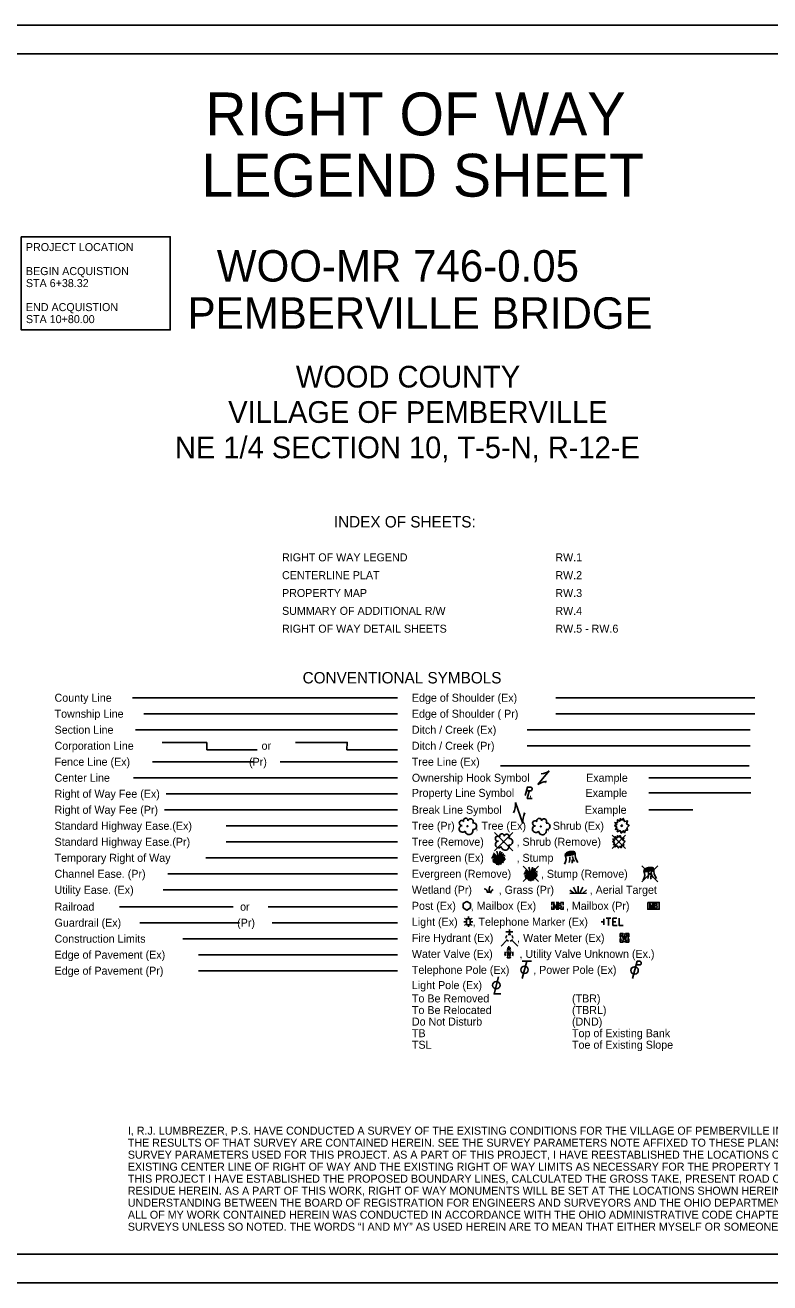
# Model space of a CAD drawing. Extents: x 0 to 34, y 0 to 22.
# Drawn here: x 9.38 to 22.4, y 0 to 22 of the extents above; entities that cross this region are included whole.
import ezdxf

# ---------------------------------------------------------------- set-up
doc = ezdxf.new("R2010")
doc.units = 0
for name, color, linetype in [('SH_Border', 7, 'Continuous'), ('SH_Cut_Line', 7, 'Continuous'), ('SH_Data', 7, 'Continuous'), ('SH_Text', 7, 'Continuous')]:
    doc.layers.add(name, color=color, linetype=linetype)

msp = doc.modelspace()

# ---------------------------------------------------------------- linework, layer by layer
at = {"layer": 'SH_Border'}
msp.add_lwpolyline([(1.5, 21.5), (33.5, 21.5), (33.5, 0.5), (1.5, 0.5)], close=True, dxfattribs=at)
at = {"layer": 'SH_Cut_Line'}
msp.add_lwpolyline([(0, 0), (34, 0), (34, 22), (0, 22)], close=True, dxfattribs=at)
at = {"layer": 'SH_Text'}
for p, q in [((11.254, 10.235), (15.893, 10.235)), ((18.66, 10.235), (22.143, 10.235)), ((11.452, 9.955), (15.893, 9.955)), ((18.66, 9.955), (22.143, 9.955)), ((11.31, 9.675), (15.893, 9.675)), ((18.159, 9.675), (22.059, 9.675)), ((11.774, 9.452), (12.556, 9.452)), ((12.556, 9.452), (12.556, 9.325)), ((12.556, 9.325), (13.437, 9.325)), ((18.159, 9.395), (22.059, 9.395)), ((11.607, 9.115), (13.38, 9.115)), ((13.837, 9.115), (15.893, 9.115)), ((17.692, 9.045), (22.042, 9.045)), ((11.275, 8.835), (15.893, 8.835)), ((18.347, 8.715), (18.547, 8.955)), ((18.447, 8.835), (18.447, 8.835)), ((20.29, 8.835), (22.072, 8.835)), ((18.147, 8.604), (18.212, 8.604)), ((11.843, 8.555), (15.893, 8.555)), ((17.954, 8.404), (18.084, 8.036)), ((18.187, 8.573), (18.187, 8.573)), ((20.29, 8.571), (22.072, 8.571)), ((11.815, 8.275), (15.893, 8.275)), ((18.019, 8.22), (18.019, 8.22)), ((20.29, 8.275), (21.055, 8.275)), ((12.893, 7.995), (15.893, 7.995)), ((12.893, 7.715), (15.893, 7.715)), ((17.587, 7.876), (17.908, 7.555)), ((17.908, 7.876), (17.587, 7.555)), ((17.748, 7.715), (17.748, 7.715)), ((19.646, 7.831), (19.878, 7.599)), ((19.878, 7.831), (19.646, 7.599)), ((19.762, 7.715), (19.762, 7.715)), ((17.658, 7.435), (17.56, 7.492)), ((17.658, 7.435), (17.571, 7.522)), ((17.658, 7.435), (17.627, 7.55)), ((17.658, 7.435), (17.69, 7.553)), ((17.658, 7.435), (17.724, 7.532)), ((17.658, 7.435), (17.75, 7.505)), ((12.539, 7.435), (15.893, 7.435)), ((17.535, 7.435), (17.658, 7.435)), ((17.658, 7.435), (17.548, 7.465)), ((17.658, 7.435), (17.551, 7.396)), ((17.658, 7.435), (17.559, 7.378)), ((17.658, 7.435), (17.56, 7.36)), ((17.658, 7.435), (17.584, 7.348)), ((17.658, 7.435), (17.6, 7.335)), ((17.658, 7.435), (17.616, 7.327)), ((17.658, 7.435), (17.627, 7.314)), ((17.658, 7.435), (17.645, 7.32)), ((17.658, 7.435), (17.777, 7.475)), ((17.658, 7.435), (17.771, 7.437)), ((17.658, 7.304), (17.658, 7.435)), ((17.658, 7.435), (17.681, 7.319)), ((17.658, 7.435), (17.706, 7.318)), ((17.658, 7.435), (17.722, 7.34)), ((17.658, 7.435), (17.748, 7.347)), ((17.658, 7.435), (17.754, 7.371)), ((17.658, 7.435), (17.77, 7.387)), ((17.658, 7.435), (17.779, 7.411)), ((18.088, 7.289), (18.356, 7.022)), ((18.356, 7.289), (18.088, 7.022)), ((18.222, 7.155), (18.191, 7.271)), ((18.222, 7.155), (18.254, 7.273)), ((18.932, 7.435), (18.932, 7.435)), ((20.168, 7.294), (20.446, 7.016)), ((20.446, 7.294), (20.168, 7.016)), ((11.876, 7.155), (15.893, 7.155)), ((18.099, 7.155), (18.222, 7.155)), ((18.222, 7.155), (18.112, 7.185)), ((18.222, 7.155), (18.115, 7.116)), ((18.222, 7.155), (18.123, 7.098)), ((18.222, 7.155), (18.124, 7.213)), ((18.222, 7.155), (18.124, 7.08)), ((18.222, 7.155), (18.135, 7.242)), ((18.222, 7.155), (18.148, 7.069)), ((18.222, 7.155), (18.164, 7.055)), ((18.222, 7.155), (18.18, 7.047)), ((18.222, 7.155), (18.191, 7.034)), ((18.222, 7.155), (18.209, 7.04)), ((18.222, 7.155), (18.288, 7.252)), ((18.222, 7.155), (18.314, 7.225)), ((18.222, 7.155), (18.341, 7.195)), ((18.222, 7.155), (18.335, 7.158)), ((18.222, 7.024), (18.222, 7.155)), ((18.222, 7.155), (18.245, 7.039)), ((18.222, 7.155), (18.27, 7.039)), ((18.222, 7.155), (18.286, 7.06)), ((18.222, 7.155), (18.312, 7.067)), ((18.222, 7.155), (18.318, 7.091)), ((18.222, 7.155), (18.334, 7.107)), ((18.222, 7.155), (18.343, 7.131)), ((18.222, 7.155), (18.222, 7.155)), ((20.307, 7.155), (20.307, 7.155)), ((20.307, 7.155), (20.307, 7.155)), ((11.793, 6.875), (15.893, 6.875)), ((18.975, 6.814), (18.907, 6.871)), ((19.024, 6.815), (18.972, 6.921)), ((19.054, 6.815), (19.052, 6.941)), ((19.084, 6.816), (19.133, 6.923)), ((19.132, 6.816), (19.199, 6.876)), ((18.665, 6.656), (18.715, 6.656)), ((18.908, 6.813), (19.2, 6.817)), ((11.031, 6.58), (13.018, 6.58)), ((13.627, 6.58), (15.893, 6.58)), ((17.083, 6.364), (17.064, 6.382)), ((17.131, 6.379), (17.131, 6.406)), ((17.197, 6.382), (17.179, 6.364)), ((18.665, 6.534), (18.715, 6.534)), ((18.69, 6.595), (18.69, 6.595)), ((20.369, 6.595), (20.369, 6.595)), ((11.386, 6.3), (13.128, 6.3)), ((13.698, 6.3), (15.893, 6.3)), ((17.079, 6.316), (17.052, 6.316)), ((17.083, 6.267), (17.064, 6.248)), ((17.131, 6.315), (17.131, 6.315)), ((17.131, 6.251), (17.131, 6.225)), ((17.197, 6.248), (17.179, 6.267)), ((17.21, 6.316), (17.183, 6.316)), ((17.849, 6.095), (17.849, 6.181)), ((19.503, 6.315), (19.454, 6.315)), ((19.503, 6.265), (19.503, 6.365)), ((12.137, 6.02), (15.893, 6.02)), ((17.807, 5.993), (17.703, 5.889)), ((17.909, 6.138), (17.789, 6.138)), ((17.849, 6.035), (17.849, 6.035)), ((17.849, 6.035), (17.849, 6.035)), ((17.891, 5.993), (17.995, 5.889)), ((19.862, 6.035), (19.862, 6.035)), ((12.41, 5.74), (15.893, 5.74)), ((17.872, 5.857), (17.808, 5.857)), ((17.84, 5.825), (17.84, 5.889)), ((17.84, 5.755), (17.84, 5.755)), ((18.153, 5.625), (18.072, 5.325)), ((18.233, 5.625), (18.073, 5.625)), ((20.082, 5.625), (20.001, 5.325)), ((20.065, 5.562), (20.124, 5.562)), ((20.082, 5.625), (20.124, 5.625)), ((12.41, 5.46), (15.893, 5.46))]:
    msp.add_line(p, q, dxfattribs=at)
for points in [[(9.311, 18.299), (11.916, 18.299), (11.916, 16.668), (9.311, 16.668)], [(20.269, 6.656), (20.469, 6.656), (20.469, 6.534), (20.269, 6.534)], [(17.097, 6.265), (17.164, 6.265), (17.164, 6.365), (17.097, 6.365)]]:
    msp.add_lwpolyline(points, close=True, dxfattribs=at)
for points in [[(14.11, 9.452), (15.014, 9.452), (15.008, 9.325), (15.893, 9.325)], [(18.126, 8.525), (18.165, 8.673), (18.217, 8.673)], [(18.201, 8.621), (18.161, 8.473), (18.248, 8.473)], [(19.811, 8.086), (19.841, 8.123), (19.862, 8.07), (19.917, 8.079), (19.9, 8.028), (19.947, 7.999), (19.904, 7.962), (19.917, 7.916), (19.879, 7.92), (19.863, 7.874), (19.841, 7.908), (19.807, 7.868), (19.786, 7.912), (19.735, 7.89), (19.744, 7.938), (19.704, 7.933), (19.728, 7.973), (19.689, 8.001), (19.726, 8.014), (19.696, 8.055), (19.742, 8.049), (19.741, 8.101), (19.778, 8.073), (19.789, 8.122), (19.811, 8.086)], [(19.759, 7.792), (19.784, 7.823), (19.802, 7.779), (19.848, 7.786), (19.834, 7.743), (19.874, 7.718), (19.838, 7.687), (19.848, 7.648), (19.816, 7.651), (19.803, 7.612), (19.784, 7.641), (19.755, 7.607), (19.737, 7.644), (19.694, 7.626), (19.702, 7.666), (19.668, 7.663), (19.688, 7.696), (19.655, 7.72), (19.686, 7.732), (19.661, 7.766), (19.7, 7.761), (19.699, 7.805), (19.731, 7.781), (19.74, 7.823), (19.759, 7.792)], [(17.038, 6.558), (17.103, 6.52), (17.167, 6.558), (17.167, 6.633), (17.103, 6.67), (17.038, 6.633), (17.038, 6.558)], [(18.59, 6.608), (18.59, 6.656), (18.639, 6.656)], [(18.626, 6.555), (18.626, 6.635), (18.655, 6.555), (18.682, 6.635), (18.682, 6.555)], [(18.742, 6.599), (18.745, 6.602), (18.747, 6.604), (18.748, 6.606), (18.748, 6.607), (18.75, 6.609), (18.75, 6.611), (18.752, 6.616), (18.752, 6.618), (18.752, 6.62), (18.751, 6.624), (18.75, 6.627), (18.748, 6.63), (18.745, 6.632), (18.742, 6.633), (18.741, 6.634), (18.738, 6.635), (18.707, 6.635), (18.707, 6.555), (18.742, 6.555), (18.746, 6.558), (18.75, 6.561), (18.753, 6.566), (18.755, 6.572), (18.755, 6.577), (18.755, 6.581), (18.754, 6.585), (18.752, 6.591), (18.748, 6.594), (18.742, 6.599), (18.707, 6.599)], [(18.741, 6.656), (18.79, 6.656), (18.79, 6.608)], [(20.304, 6.555), (20.304, 6.635), (20.333, 6.555), (20.36, 6.635), (20.36, 6.555)], [(20.42, 6.599), (20.423, 6.602), (20.425, 6.604), (20.426, 6.606), (20.427, 6.607), (20.428, 6.609), (20.428, 6.611), (20.43, 6.616), (20.43, 6.618), (20.43, 6.62), (20.429, 6.624), (20.428, 6.627), (20.426, 6.63), (20.423, 6.632), (20.42, 6.633), (20.419, 6.634), (20.416, 6.635), (20.385, 6.635), (20.385, 6.555), (20.42, 6.555), (20.424, 6.558), (20.428, 6.561), (20.431, 6.566), (20.433, 6.572), (20.434, 6.577), (20.434, 6.581), (20.432, 6.585), (20.43, 6.591), (20.427, 6.594), (20.42, 6.599), (20.385, 6.599)], [(18.639, 6.534), (18.59, 6.534), (18.59, 6.583)], [(18.79, 6.583), (18.79, 6.534), (18.741, 6.534)], [(19.544, 6.377), (19.622, 6.377)], [(19.584, 6.377), (19.584, 6.252)], [(19.729, 6.377), (19.661, 6.377), (19.661, 6.252), (19.734, 6.252)], [(19.661, 6.315), (19.71, 6.315)], [(19.769, 6.377), (19.769, 6.252), (19.837, 6.252)], [(19.842, 6.11), (19.787, 6.11), (19.787, 6.055)], [(19.787, 6.015), (19.787, 5.96), (19.842, 5.96)], [(19.829, 6.08), (19.846, 5.99), (19.862, 6.08), (19.879, 5.99), (19.896, 6.08)], [(19.937, 6.055), (19.937, 6.11), (19.882, 6.11)], [(19.882, 5.96), (19.937, 5.96), (19.937, 6.015)], [(17.808, 5.796), (17.824, 5.71), (17.84, 5.796), (17.856, 5.71), (17.872, 5.796)], [(17.66, 5.354), (17.581, 5.055), (17.699, 5.055)]]:
    msp.add_lwpolyline(points, dxfattribs=at)
for centre, radius in [((17.115, 7.987), 0.0084), ((18.399, 7.984), 0.0072), ((19.815, 7.995), 0.0115), ((17.748, 7.715), 0.0072), ((19.762, 7.715), 0.00979), ((19.862, 6.035), 0.0675), ((18.113, 5.475), 0.065), ((20.039, 5.465), 0.065), ((17.621, 5.206), 0.065)]:
    msp.add_circle(centre, radius, dxfattribs=at)
for centre, radius, start, end in [((18.389, 9.17), 0.267, 273.6945, 306.337), ((18.212, 8.639), 0.0345, 270.471, 81.3281), ((18.505, 8.5), 0.267, 93.6945, 126.337), ((17.622, 8.371), 0.334, 332.9422, 5.5848), ((18.416, 8.068), 0.334, 152.9422, 185.5848), ((17.029, 7.941), 0.0592, 96.1722, 320.5737), ((17.015, 8.043), 0.0441, 39.0625, 279.5412), ((17.085, 8.088), 0.0395, 354.0047, 205.9741), ((17.143, 7.909), 0.0685, 184.9476, 19.4572), ((17.169, 8.072), 0.0466, 323.83, 165.0376), ((17.218, 7.988), 0.0574, 259.1453, 101.4596), ((18.314, 7.937), 0.0592, 96.1722, 320.5737), ((18.3, 8.04), 0.0441, 39.0625, 279.5412), ((18.37, 8.085), 0.0395, 354.0047, 205.9741), ((18.428, 7.906), 0.0685, 184.9476, 19.4572), ((18.454, 8.069), 0.0466, 323.83, 165.0376), ((18.503, 7.985), 0.0574, 259.1453, 101.4596), ((17.662, 7.669), 0.0592, 96.1722, 320.5737), ((17.648, 7.771), 0.0441, 39.0625, 279.5412), ((17.718, 7.816), 0.0395, 354.0047, 205.9741), ((17.802, 7.8), 0.0466, 323.83, 165.0376), ((17.851, 7.716), 0.0574, 259.1453, 101.4596), ((17.776, 7.637), 0.0685, 184.9476, 19.4572), ((18.64, 7.418), 0.2, 331.5338, 20.9269), ((19.212, 7.492), 0.215, 171.4106, 219.9194), ((18.656, 7.437), 0.253, 340.7938, 3.5481), ((19.127, 7.395), 0.182, 178.7926, 197.1224), ((19.257, 7.538), 0.316, 194.9653, 212.1216), ((20.016, 7.138), 0.2, 331.5338, 20.9269), ((20.031, 7.157), 0.253, 340.7938, 3.5481), ((20.503, 7.115), 0.182, 178.7926, 197.1224), ((20.633, 7.258), 0.316, 194.9653, 212.1216), ((20.588, 7.212), 0.215, 171.4106, 219.9194), ((17.849, 6.035), 0.06, 140.021, 184.0629), ((17.849, 6.035), 0.06, 211.8788, 255.8479), ((17.849, 6.035), 0.06, 68.1395, 112.038), ((17.849, 6.035), 0.06, 283.8239, 329.9097), ((17.849, 6.035), 0.06, 356.0165, 39.9889), ((17.84, 5.755), 0.07, 150.0184, 209.9816), ((17.84, 5.755), 0.07, 60.0184, 120.0157), ((17.84, 5.755), 0.07, 330.0184, 29.9816), ((17.84, 5.755), 0.07, 239.9843, 299.9816), ((20.125, 5.593), 0.0319, 268.8767, 91.1233)]:
    msp.add_arc(centre, radius, start, end, dxfattribs=at)
for centre, major_axis in [((18.913, 7.511), (0.0868, 0.0187)), ((18.913, 7.511), (0.0651, 0.0141)), ((18.913, 7.511), (0.0488, 0.0105)), ((18.913, 7.511), (0.0275, 0.0059)), ((18.913, 7.511), (0.0154, 0.0033)), ((20.289, 7.231), (0.0868, 0.0187)), ((20.289, 7.231), (0.0651, 0.0141)), ((20.289, 7.231), (0.0488, 0.0105)), ((20.289, 7.231), (0.0275, 0.0059)), ((20.289, 7.231), (0.0154, 0.0033))]:
    msp.add_ellipse(centre, major_axis=major_axis, ratio=0.36865, dxfattribs=at)
for points in [[(17.407, 6.891), (17.448, 6.873), (17.466, 6.82)], [(17.494, 6.824), (17.494, 6.871), (17.5, 6.916), (17.509, 6.936)], [(17.522, 6.817), (17.534, 6.855), (17.563, 6.879)]]:
    msp.add_spline(points, degree=3, dxfattribs=at)

# ---------------------------------------------------------------- texts
at = {"layer": 'SH_Data'}
for s, height, p in [('RIGHT OF WAY', 0.75, (12.527, 20.072)), ('LEGEND SHEET', 0.75, (12.458, 19)), ('WOO-MR 746-0.05', 0.55, (12.732, 17.514)), ('PEMBERVILLE BRIDGE', 0.55, (12.221, 16.689)), ('WOOD COUNTY', 0.38, (14.114, 15.661)), ('VILLAGE OF PEMBERVILLE', 0.38, (12.931, 15.043)), ('NE 1/4 SECTION 10, T-5-N, R-12-E', 0.38, (11.998, 14.424)), ('INDEX OF SHEETS:', 0.2, (14.778, 13.213)), ('RIGHT OF WAY LEGEND', 0.14, (13.872, 12.621)), ('RW.1', 0.14, (18.653, 12.621)), ('CENTERLINE PLAT', 0.14, (13.872, 12.309)), ('RW.2', 0.14, (18.653, 12.309)), ('PROPERTY MAP', 0.14, (13.872, 11.997)), ('RW.3', 0.14, (18.653, 11.997)), ('SUMMARY OF ADDITIONAL R/W', 0.14, (13.872, 11.685)), ('RW.4', 0.14, (18.653, 11.685)), ('RIGHT OF WAY DETAIL SHEETS', 0.14, (13.872, 11.373)), ('RW.5 - RW.6', 0.14, (18.653, 11.373)), ('To Be Removed', 0.14, (16.144, 4.905)), ('To Be Relocated                 ', 0.14, (16.144, 4.702)), ('(TBR)', 0.14, (18.944, 4.905)), ('(TBRL)', 0.14, (18.944, 4.702)), ('Do Not Disturb', 0.14, (16.144, 4.5)), ('(DND)', 0.14, (18.944, 4.5)), ('TB', 0.14, (16.144, 4.297)), ('Top of Existing Bank', 0.14, (18.944, 4.297)), ('TSL', 0.14, (16.144, 4.095)), ('Toe of Existing Slope', 0.14, (18.944, 4.095))]:
    msp.add_text(s, height=height, dxfattribs=at).set_placement(p)
at = {"layer": 'SH_Text'}
for s, height, p in [('PROJECT LOCATION', 0.14, (9.392, 18.048)), ('BEGIN ACQUISTION', 0.14, (9.392, 17.628)), ('STA 6+38.32', 0.14, (9.392, 17.418)), ('END ACQUISTION', 0.14, (9.392, 16.998)), ('STA 10+80.00', 0.14, (9.392, 16.788)), ('CONVENTIONAL SYMBOLS', 0.2, (14.232, 10.485)), ('County Line', 0.14, (9.893, 10.165)), ('Edge of Shoulder (Ex)', 0.14, (16.143, 10.165)), ('Township Line', 0.14, (9.893, 9.885)), ('Edge of Shoulder ( Pr)', 0.14, (16.143, 9.885)), ('Section Line', 0.14, (9.893, 9.605)), ('Ditch / Creek (Ex)', 0.14, (16.143, 9.605)), ('Corporation Line                                           or', 0.14, (9.893, 9.325)), ('Ditch / Creek (Pr)', 0.14, (16.143, 9.325)), ('Fence Line (Ex)                                        (Pr)', 0.14, (9.893, 9.045)), ('Tree Line (Ex)', 0.14, (16.143, 9.045)), ('Center Line', 0.14, (9.893, 8.765)), ('Ownership Hook Symbol     ,             Example', 0.14, (16.143, 8.765)), ('Right of Way Fee (Ex)', 0.14, (9.893, 8.485)), ('Property Line Symbol     ,                  Example', 0.14, (16.143, 8.501)), ('Right of Way Fee (Pr)', 0.14, (9.893, 8.205)), ('Break Line Symbol       ,                    Example', 0.14, (16.143, 8.205)), ('Standard Highway Ease.(Ex)', 0.14, (9.893, 7.925)), ('Tree (Pr)       , Tree (Ex)       , Shrub (Ex)', 0.14, (16.143, 7.925)), ('Standard Highway Ease.(Pr)', 0.14, (9.893, 7.645)), ('Tree (Remove)           , Shrub (Remove)', 0.14, (16.143, 7.645)), ('Temporary Right of Way', 0.14, (9.893, 7.365)), ('Evergreen (Ex)           , Stump ', 0.14, (16.143, 7.365)), ('Channel Ease. (Pr)', 0.14, (9.893, 7.085)), ('Evergreen (Remove)          , Stump (Remove)', 0.14, (16.143, 7.085)), ('Utility Ease. (Ex)', 0.14, (9.893, 6.805)), ('Wetland (Pr)         , Grass (Pr)            , Aerial Target    ', 0.14, (16.143, 6.805)), ('Railroad                                                 or', 0.14, (9.893, 6.51)), ('Post (Ex)     , Mailbox (Ex)          , Mailbox (Pr)', 0.14, (16.143, 6.525)), ('Light (Ex)     , Telephone Marker (Ex)     ', 0.14, (16.143, 6.245)), ('Guardrail (Ex)                                       (Pr)', 0.14, (9.893, 6.23)), ('Construction Limits', 0.14, (9.893, 5.95)), ('Fire Hydrant (Ex)        , Water Meter (Ex)', 0.14, (16.143, 5.965)), ('Edge of Pavement (Ex)', 0.14, (9.893, 5.67)), ('Water Valve (Ex)         , Utility Valve Unknown (Ex.)', 0.14, (16.143, 5.685)), ('Edge of Pavement (Pr)', 0.14, (9.893, 5.39)), ('Telephone Pole (Ex)        , Power Pole (Ex)', 0.14, (16.143, 5.405)), ('Light Pole (Ex)     ', 0.14, (16.143, 5.138)), ('I, R.J. LUMBREZER, P.S. HAVE CONDUCTED A SURVEY OF THE EXISTING CONDITIONS FOR THE VILLAGE OF PEMBERVILLE IN NOVEMBER AND DECEMBER OF 2023.', 0.14, (11.175, 2.592)), ('THE RESULTS OF THAT SURVEY ARE CONTAINED HEREIN. SEE THE SURVEY PARAMETERS NOTE AFFIXED TO THESE PLANS FOR THE HORIZONTAL AND VERTICAL', 0.14, (11.175, 2.382)), ('SURVEY PARAMETERS USED FOR THIS PROJECT. AS A PART OF THIS PROJECT, I HAVE REESTABLISHED THE LOCATIONS OF THE EXISTING BOUNDARY LINES, THE', 0.14, (11.175, 2.172)), ('EXISTING CENTER LINE OF RIGHT OF WAY AND THE EXISTING RIGHT OF WAY LIMITS AS NECESSARY FOR THE PROPERTY TAKES CONTAINED HEREIN. AS A PART OF', 0.14, (11.175, 1.962)), ('THIS PROJECT I HAVE ESTABLISHED THE PROPOSED BOUNDARY LINES, CALCULATED THE GROSS TAKE, PRESENT ROAD OCCUPIED (PRO), NET TAKE AND NET', 0.14, (11.175, 1.752)), ('RESIDUE HEREIN. AS A PART OF THIS WORK, RIGHT OF WAY MONUMENTS WILL BE SET AT THE LOCATIONS SHOWN HEREIN PER THE MEMORANDUM OF', 0.14, (11.175, 1.542)), ('UNDERSTANDING BETWEEN THE BOARD OF REGISTRATION FOR ENGINEERS AND SURVEYORS AND THE OHIO DEPARTMENT OF TRANSPORTATION DATED 9-22-2010.', 0.14, (11.175, 1.332)), ('ALL OF MY WORK CONTAINED HEREIN WAS CONDUCTED IN ACCORDANCE WITH THE OHIO ADMINISTRATIVE CODE CHAPTER 4733-37 STANDARDS FOR BOUNDARY', 0.14, (11.175, 1.122)), ('SURVEYS UNLESS SO NOTED. THE WORDS “I AND MY” AS USED HEREIN ARE TO MEAN THAT EITHER MYSELF OR SOMEONE WORKING UNDER MY DIRECT SUPERVISION.', 0.14, (11.175, 0.912))]:
    msp.add_text(s, height=height, dxfattribs=at).set_placement(p)

doc.saveas('drawing.dxf')
